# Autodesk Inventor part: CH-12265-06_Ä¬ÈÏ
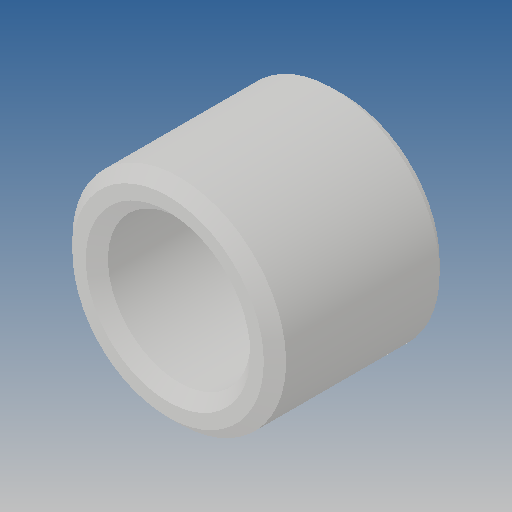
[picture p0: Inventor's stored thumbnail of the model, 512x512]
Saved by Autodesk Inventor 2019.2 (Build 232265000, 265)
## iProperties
Created: 2010-06
Part Number: CH-12265-06_Ä¬ÈÏ
Material: Ogólny
Document SubType Name: Modeling
Designer: CADENGINEERING4
Density: 1 g/cm^3
Appearance: Domyślna
Author: CADENGINEERING4
Revision Number: ÈÎºÎ
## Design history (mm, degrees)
feature "NONE"
node "Bryła1"
